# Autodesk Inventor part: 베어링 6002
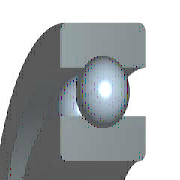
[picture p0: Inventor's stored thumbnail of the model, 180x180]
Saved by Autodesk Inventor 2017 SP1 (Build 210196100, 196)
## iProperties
Created: 2012-02
Part Number: 베어링 6002
Material: 강철, 연강
Description: 깊은 그루브 볼 베어링
Document SubType Name: Modeling
Standard: KS B 2023
Designer: mduedu
Standards Organization: KS
Language: ko-KR
Size Designation: 6002 - 15 x 32 x 9
Categories: <MemberInstance><Categories><Category DisplayName="샤프트 부품" InternalName="7f7aeb1f-a693-4053-b835-cee3144e0d98" Mnemonic="SHFT"><Category DisplayName="베어링" Inter
Density: 7.86 g/cm^3
Mass: 29.8124 g
Surface Area: 39.9079 cm^2
Volume: 3.79293 cm^3
Appearance: 분홍색
IsCustomPart: 1
Author: mduedu
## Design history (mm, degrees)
sketch "스케치" dims "d0" = 4.42 (= -0.26 x WD + 0.26 x BD)
  geometry: L1 (2.29, 11.75)-(6.71, 11.75); L2 (4.5, 11.75)-(4.5, 9.54); L3 (4.5, 11.75)-(4.5, 13.96); L4 (2.858, 10.271)-(0, 10.271); L5 (0, 7.5)-(9, 7.5); L6 (2.858, 13.229)-(0, 13.229); L7 (0, 16)-(9, 16); L8 (9, 7.5)-(9, 10.271); L9 (6.142, 10.271)-(9, 10.271); L10 (6.142, 13.229)-(9, 13.229); L11 (9, 16)-(9, 13.229); L12 (-1.4, 0)-(8.4, 0) reference; L13 (0, -0.3)-(0, 5.3) reference
  constraints: 22 end point, 4 point on line, 2 collinear, 2 perpendicular, 2 symmetric about line, 1 midpoint, 1 parallel, 14 other
  dimensions: "d9" = 15 diameter of L5 L12 (= WD); "d11" = 32 diameter of L7 L12 (= BD); "d12" = 9 distance between parallel lines of L8 L13 (= KB); "d13" = 20.542 diameter of L9 L12 (= 0.326 x BD + 0.674 x WD)
revolve "본체" stored, may be unused: angle "d6" = 90 deg
revolve "볼" stored, may be unused: angle "d7" = 90 deg
pattern_circular "IDS_ARRAYBALL[SIMPL:T]" dims angle "d3" = 360 deg
body "Solid1"
fillet "모깎기1" dims "d1" = 0.3 (= KRS)
other parameters: "WD" = 15 [user parameter; used in 5 equation terms], "BD" = 32 [user parameter; used in 5 equation terms], "KB" = 9 [user parameter; used in 1 equation term], "KRS" = 0.3 [user parameter; used in 1 equation term], "d4" = 0, "d5" = 0, "d8" = 0, "d14" = 0, "d15" = 0, "BBA" = 0 [user parameter], "BC0" = 2850000 [user parameter], "BC" = 5590000 [user parameter], "BR" = 16 (= 0.5 x BD) [user parameter], "WR" = 7.5 (= 0.5 x WD) [user parameter]
